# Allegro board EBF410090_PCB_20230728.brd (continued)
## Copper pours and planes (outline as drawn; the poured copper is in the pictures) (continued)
GND on BOTTOM: 69.22,21.26 69.29,21.08 69.47,21 73.66,21 73.84,21.08 73.91,21.26 73.91,25.37 73.84,25.55 73.66,25.63 69.47,25.63 69.29,25.55 69.22,25.37
GND on BOTTOM: 10.39,56.72 10.39,59.97 10.79,60.37 10.79,62.15 10.92,62.28 13.13,62.28 13.34,62.08 13.34,56.92 13.13,56.72
GND on BOTTOM: outline of 101 points within 0.51,8.51 136.49,89.49 ; 1 cut-out
GND on BOTTOM: 54.61,27.43 54.68,27.25 54.86,27.18 61.85,27.18 62.03,27.25 62.1,27.43 62.1,30.1 62.03,30.28 61.85,30.35 54.86,30.35 54.68,30.28 54.61,30.1
GND on BOTTOM: 127.08,84.07 127.08,78.82 125.15,78.82 125.15,80.47 124.84,80.77 123.65,80.77 123.47,80.95 123.47,83.49 124.05,84.07
GND on BOTTOM: 9.14,27.56 9.22,27.38 9.4,27.3 12.19,27.3 12.37,27.38 12.45,27.56 12.45,30.35 12.37,30.53 12.19,30.61 9.4,30.61 9.22,30.53 9.14,30.35
GND on BOTTOM: 7.01,51.61 7.08,51.43 7.26,51.36 9.25,51.36 9.43,51.43 9.5,51.61 9.5,55.8 9.43,55.98 9.25,56.06 7.26,56.06 7.08,55.98 7.01,55.8
GND on BOTTOM: 111.84,40.61 111.91,40.43 112.09,40.36 119.71,40.36 119.89,40.43 119.96,40.61 119.96,46.02 119.89,46.2 119.71,46.28 117.2,46.28 116.69,46.79 116.69,58.19 116.43,58.44 111.71,58.44 111.53,58.27 111.53,46.15 111.84,45.85
GND on BOTTOM: 131.34,76.07 131.34,78.26 131.09,78.51 128.63,78.51 128.19,78.94 128.19,80.34 128.63,80.77 130.91,80.77 131.32,80.36 131.32,79.81 132.33,78.79 132.33,76.07 132.13,75.87 131.55,75.87
GND on BOTTOM: 12.57,69.72 12.39,69.8 12.32,69.98 12.32,73.1 12.33,73.16 12.34,73.21 12.34,71.8 12.42,71.63 12.6,71.55 14.05,71.55 14.23,71.63 14.3,71.8 14.3,73.3 14.3,73.35 18.08,73.35 18.26,73.28 18.34,73.1 18.34,69.98 18.26,69.8 18.08,69.72
GND on BOTTOM: 127.56,61.92 127.63,61.74 127.81,61.67 129.34,61.67 129.52,61.74 129.59,61.92 129.59,64.03 129.52,64.21 129.34,64.29 127.81,64.29 127.63,64.21 127.56,64.03
GND on BOTTOM: 20.6,69.67 20.67,69.49 20.85,69.42 21.92,69.42 22.1,69.49 22.17,69.67 22.17,71.25 22.1,71.43 21.92,71.5 20.85,71.5 20.67,71.43 20.6,71.25
GND on BOTTOM: 72.14,26.49 72.21,26.31 72.39,26.24 74.4,26.24 74.58,26.31 74.65,26.49 74.65,28.02 74.58,28.19 74.4,28.27 72.39,28.27 72.21,28.19 72.14,28.02
GND on BOTTOM: 63.75,64.9 63.83,64.72 64.01,64.64 67.56,64.64 67.74,64.72 67.82,64.9 67.82,67.05 67.74,67.23 67.56,67.31 64.01,67.31 63.83,67.23 63.75,67.05
GND on BOTTOM: 123.49,19.28 123.57,19.1 123.75,19.02 125.68,19.02 125.86,19.1 125.93,19.28 125.93,25.86 125.86,26.04 125.68,26.11 123.75,26.11 123.57,26.04 123.49,25.86
GND on BOTTOM: 18.54,67.56 18.62,67.38 18.8,67.31 21.89,67.31 22.07,67.38 22.15,67.56 22.15,68.07 22.07,68.25 21.89,68.32 18.8,68.32 18.62,68.25 18.54,68.07
GND on BOTTOM: 14.53,67.89 14.53,64.06 14.22,63.75 11.07,63.75 10.79,63.47 10.79,61.67 10.95,61.52 16.03,61.52 16.26,61.75 16.26,67.66 16.03,67.89
GND on BOTTOM: 3.53,56.69 3.53,65.18 3.81,65.45 4.6,65.45 4.75,65.3 4.75,63.35 4.98,63.12 5.77,63.12 6.17,62.71 6.17,59.51 6.5,59.18 6.5,58.62 5.64,58.62 5.46,58.44 5.46,56.95 5.21,56.69
GND on BOTTOM: 96.14,43.79 96.21,43.61 96.39,43.53 99.62,43.53 99.8,43.61 99.87,43.79 99.87,45.21 99.8,45.39 99.62,45.46 96.39,45.46 96.21,45.39 96.14,45.21
GND on BOTTOM: 41.27,27.43 41.35,27.25 41.53,27.18 48.51,27.18 48.69,27.25 48.77,27.43 48.77,30.1 48.69,30.28 48.51,30.35 41.53,30.35 41.35,30.28 41.27,30.1
GND on BOTTOM: 100.58,40.11 100.66,39.93 100.84,39.85 103.76,39.85 103.94,39.93 104.01,40.11 104.01,42.62 103.94,42.8 103.76,42.87 100.84,42.87 100.66,42.8 100.58,42.62
GND on BOTTOM: 25.43,70.08 25.5,69.9 25.68,69.82 29.16,69.82 29.34,69.9 29.41,70.08 29.41,72.47 29.34,72.64 29.16,72.72 25.68,72.72 25.5,72.64 25.43,72.47
GND on BOTTOM: 18.92,27.63 19,27.45 19.18,27.38 30.05,27.38 30.23,27.45 30.3,27.63 30.3,30.2 30.23,30.38 30.05,30.45 19.18,30.45 19,30.38 18.92,30.2
GND on BOTTOM: 7.29,48.34 7.29,49.76 6.99,50.06 6.99,52.86 6.81,53.03 5.05,53.03 5,52.98 5,51.61 5.31,51.31 5.79,51.31 5.87,51.23 5.87,48.49 6.02,48.34
GND on GND02: 3.05,8.51 1.25,9.25 0.51,11.05 0.51,86.95 1.25,88.75 3.05,89.49 133.95,89.49 135.75,88.75 136.49,86.95 136.49,11.05 135.75,9.25 133.95,8.51
GND on ART03: 102.72,24.26 102.72,15.95 106.83,15.95 106.83,24.26
GND on ART03: 3.05,8.51 1.25,9.25 0.51,11.05 0.51,25.93 17.02,25.93 19.84,23.11 27.89,23.11 28.55,22.45 28.55,18.26 28.78,18.03 33.15,18.03 33.78,17.4 41.53,17.4 41.78,17.14 41.78,13.59 42.04,13.33 42.67,13.33 43.56,14.22 44.7,14.22 45.47,13.46 70.74,13.46 72.39,11.81 119.76,11.81 120.78,12.83 122.05,12.83 122.94,13.71 129.54,13.71 131.19,15.37 134.11,15.37 135.41,16.66 135.41,53.44 135.94,53.97 135.94,82.02 135.64,82.32 131.17,82.32 129.46,84.02 129.46,88.11 128.8,88.77 52.25,88.77 51.31,87.83 51.31,81.74 50.11,80.54 4.95,80.54 4.6,80.19 4.6,76.76 4.09,76.25 1.98,76.25 1.04,75.31 1.04,26.52 0.97,26.44 0.51,26.44 0.51,86.95 1.25,88.75 3.05,89.49 133.95,89.49 135.75,88.75 136.49,86.95 136.49,11.05 135.75,9.25 133.95,8.51
GND on ART04: 84.28,53.08 84.35,52.91 84.53,52.83 103.05,52.83 103.23,52.91 103.3,53.08 103.3,73.81 103.23,73.99 103.05,74.07 84.53,74.07 84.35,73.99 84.28,73.81
GND on ART04: 36.14,40.89 36.22,40.71 36.4,40.64 47.85,40.64 48.03,40.71 48.11,40.89 48.11,67.51 48.03,67.69 47.85,67.77 36.4,67.77 36.22,67.69 36.14,67.51
VCC3V3_SYS on TOP: 119.51,66.27 119.58,66.09 119.76,66.01 122.3,66.01 122.48,66.09 122.56,66.27 122.56,66.62 122.48,66.8 122.3,66.88 119.76,66.88 119.58,66.8 119.51,66.62
VCC3V3_SYS on TOP: 5.21,46.23 5.21,45.72 5.33,45.59 7.75,45.59 7.87,45.72 7.87,47.62 6.99,47.62 6.6,47.24 5.84,47.24 5.71,47.12 5.71,46.48 5.59,46.35 5.33,46.35
VCC3V3_SYS on TOP: 119.51,44.17 119.58,43.99 119.76,43.92 122.3,43.92 122.48,43.99 122.56,44.17 122.56,44.53 122.48,44.7 122.3,44.78 119.76,44.78 119.58,44.7 119.51,44.53
VCC3V3_SYS on BOTTOM: 2.29,47.7 7.54,47.7 7.87,47.37 7.87,45.59 7.8,45.52 2.51,45.52 2.29,45.74
VCC3V3_SYS on BOTTOM: 70.26,26.49 70.33,26.31 70.51,26.24 71.73,26.24 71.91,26.31 71.98,26.49 71.98,28.02 71.91,28.19 71.73,28.27 70.51,28.27 70.33,28.19 70.26,28.02
VCC3V3_SYS on BOTTOM: 11.3,30.99 11.38,30.81 11.56,30.73 12.83,30.73 13.01,30.81 13.08,30.99 13.08,32.13 13.01,32.31 12.83,32.38 11.56,32.38 11.38,32.31 11.3,32.13
VCC3V3_SYS on BOTTOM: 11.3,34.8 11.38,34.62 11.56,34.54 12.83,34.54 13.01,34.62 13.08,34.8 13.08,35.94 13.01,36.12 12.83,36.19 11.56,36.19 11.38,36.12 11.3,35.94
VCC3V3_SYS on ART04: 16.9,24.01 18.69,22.22 65.79,22.22 66.04,21.97 66.04,18.41 66.37,18.08 128.91,18.08 129.97,19.15 129.97,44.07 129.41,44.63 118.31,44.63 117.14,45.8 117.14,51 117.88,51.74 124.41,51.74 124.99,52.32 124.99,68.5 124.54,68.96 119.05,68.96 118.62,68.53 118.62,62.69 118.92,62.38 121.39,62.38 121.67,62.1 121.67,57.91 121.41,57.66 114.1,57.66 113.61,57.17 113.61,41.12 114.07,40.66 121.44,40.66 121.97,40.13 121.97,33.6 122.33,33.25 125.27,33.25 125.73,32.79 125.73,25.4 125.58,25.25 71.91,25.25 71.91,26.62 71.63,26.9 13.87,26.9 13.39,27.38 13.39,35.36 13.37,35.37 13.37,37.98 13.11,38.25 11.48,38.25 11.23,38.51 11.23,44.6 10.97,44.86 7.85,44.86 7.75,44.96 7.75,45.97 7.62,46.1 4.7,46.1 4.57,45.97 4.57,24.26 4.83,24 4.84,24.01
VCC5V0_SYS on TOP: 13.16,50.06 14.38,50.06 14.53,50.21 14.53,52.55 14.91,52.93 14.91,60.78 15.16,61.04 15.16,63.27 13.72,63.27 13.72,57.78 13.56,57.63 13.56,53.44 13,52.88 13,50.21
VCC5V0_SYS on TOP: 119.51,36.04 119.58,35.86 119.76,35.79 122.3,35.79 122.48,35.86 122.56,36.04 122.56,36.4 122.48,36.58 122.3,36.65 119.76,36.65 119.58,36.58 119.51,36.4
VCC5V0_SYS on TOP: 119.51,39.34 119.58,39.16 119.76,39.09 122.3,39.09 122.48,39.16 122.56,39.34 122.56,39.7 122.48,39.88 122.3,39.95 119.76,39.95 119.58,39.88 119.51,39.7
VCC5V0_SYS on TOP: 119.63,58.14 119.71,57.96 119.89,57.89 122.43,57.89 122.61,57.96 122.68,58.14 122.68,58.5 122.61,58.67 122.43,58.75 119.89,58.75 119.71,58.67 119.63,58.5
VCC5V0_SYS on TOP: 119.51,61.44 119.58,61.26 119.76,61.19 122.3,61.19 122.48,61.26 122.56,61.44 122.56,61.8 122.48,61.98 122.3,62.05 119.76,62.05 119.58,61.98 119.51,61.8
VCC5V0_SYS on BOTTOM: 18.85,51.66 18.92,51.48 19.1,51.41 19.94,51.41 20.12,51.48 20.19,51.66 20.19,52.86 20.12,53.04 19.94,53.11 19.1,53.11 18.92,53.04 18.85,52.86
VCC5V0_SYS on BOTTOM: 9.09,46.28 14.17,46.28 14.43,46.53 14.43,52.37 14.17,52.63 13.11,52.63 12.85,52.37 12.85,47.93 12.6,47.67 9.09,47.67
VCC5V0_SYS on ART04: 13.06,50.04 16.84,50.04 17.14,49.73 17.14,45.39 17.55,44.98 21.97,44.98 22.66,44.3 22.66,30.89 23.29,30.25 93.24,30.25 94.08,31.09 94.08,41.3 94.64,41.86 99.95,41.86 100.48,41.32 100.48,36.88 101.04,36.32 116.92,36.32 117.35,35.89 121.08,35.89 121.31,36.12 121.31,39.88 121.06,40.13 113.54,40.13 113.13,40.54 113.13,57.61 113.51,57.99 120.88,57.99 121.28,58.39 121.28,61.67 120.83,62.13 109.58,62.13 109.09,61.64 109.09,49.53 108.2,48.64 87.55,48.64 86.92,48 86.92,33.88 86.33,33.3 29.9,33.3 28.91,34.29 28.91,53.8 28.47,54.23 13.41,54.23 13.06,53.87
VCC5V0_SYS_2 on BOTTOM: 11.3,38.73 11.38,38.55 11.56,38.48 12.83,38.48 13.01,38.55 13.08,38.73 13.08,39.88 13.01,40.06 12.83,40.13 11.56,40.13 11.38,40.06 11.3,39.88
VCC5V0_SYS_2 on BOTTOM: 106.55,84.58 106.63,84.4 106.81,84.33 107.95,84.33 108.13,84.4 108.2,84.58 108.2,85.85 108.13,86.03 107.95,86.1 106.81,86.1 106.63,86.03 106.55,85.85
VCC5V0_SYS_2 on BOTTOM: 121.51,84.38 121.59,84.2 121.77,84.12 123.29,84.12 123.47,84.2 123.55,84.38 123.55,85.8 123.47,85.98 123.29,86.05 121.77,86.05 121.59,85.98 121.51,85.8
VCC5V0_SYS_2 on BOTTOM: 11.13,65.38 11.13,64.54 11.3,64.36 13.94,64.36 13.94,67 14.17,67.23 14.17,67.84 14.35,68.02 17.68,68.02 17.88,68.22 17.88,69.24 17.6,69.52 13.69,69.52 13.34,69.16 11.58,69.16 11.1,68.68 11.1,65.4
VCC5V0_SYS_2 on ART04: 29.97,33.63 29.29,34.31 29.29,53.92 28.7,54.51 26.64,54.51 26.49,54.66 26.49,60.02 26.04,60.48 24.82,60.48 24.46,60.83 24.46,66.34 24.13,66.67 8.89,66.67 8.51,66.29 8.51,48.77 9.78,47.5 13,47.5 13.36,47.14 13.36,38.76 13.13,38.53 11.61,38.53 11.43,38.71 11.43,44.63 11,45.06 8.15,45.06 8,45.21 8,46.1 7.75,46.35 4.83,46.35 4.57,46.61 4.57,72.9 4.83,73.15 31.24,73.15 31.52,72.87 31.52,37.54 32.08,36.98 48.34,36.98 49.68,35.64 62.76,35.64 63.45,36.32 82.4,36.32 83.21,37.13 83.21,51.26 83.95,51.99 105.66,51.99 106.43,52.75 106.43,68.55 106.81,68.93 114.68,68.93 115.21,69.47 115.21,74.55 114.38,75.39 114.38,78.71 113.97,79.12 106.86,79.12 106.4,79.58 106.4,84.68 106.86,85.14 109.5,85.14 109.75,84.89 122,84.89 122.33,84.56 122.33,82.6 122.12,82.4 118.64,82.4 118.26,82.02 118.26,62.71 117.98,62.43 109.35,62.43 108.71,61.8 108.71,49.81 108.05,49.15 87.3,49.15 86.46,48.31 86.46,34.11 85.98,33.63
VCC_12V on TOP: 123.37,31.65 123.44,31.47 123.62,31.39 124.59,31.39 124.77,31.47 124.84,31.65 124.84,34.06 124.77,34.24 124.59,34.31 123.62,34.31 123.44,34.24 123.37,34.06
VCC_12V on TOP: 11.25,77.42 13.74,77.42 14.1,77.06 14.1,67.66 14.48,67.28 16.79,67.28 17.12,66.95 17.12,64.54 14.1,64.54 12.88,63.32 12.88,60.27 12.34,59.74 1.78,59.74 1.6,59.92 1.6,61.52 1.8,61.72 6.02,61.72 6.48,62.18 6.48,64.54 7.04,65.1 9.88,65.1 10.13,65.35 10.13,68.58 10.87,69.32 10.87,77.04
VCC_12V on BOTTOM: 8.51,55.47 9.78,55.47 9.96,55.65 9.96,60.37 10.34,60.76 10.34,62.13 10.36,62.15 10.36,63.17 10.24,63.3 9.02,63.3 8.84,63.12 8.84,56.49 8.51,56.16
VCC_12V on BOTTOM: 96.34,41.22 96.42,41.04 96.6,40.97 100.63,40.97 100.81,41.04 100.89,41.22 100.89,43.03 100.81,43.21 100.63,43.28 96.6,43.28 96.42,43.21 96.34,43.03
VCC_12V on BOTTOM: 1.65,55.47 2.57,55.47 2.57,56.54 2.74,56.72 3.1,56.72 3.1,63.91 2.82,64.18 2.82,65.28 1.68,65.28 1.45,65.05 1.45,55.68
VCC_12V on BOTTOM: 16,43.81 16.08,43.63 16.26,43.56 17.53,43.56 17.71,43.63 17.78,43.81 17.78,44.96 17.71,45.14 17.53,45.21 16.26,45.21 16.08,45.14 16,44.96
VCC_12V on ART04: 8.84,48.94 10.03,47.75 13.23,47.75 13.67,47.32 13.67,27.66 14.2,27.13 71.75,27.13 72.14,26.75 72.14,25.65 72.24,25.55 124.74,25.55 125.37,26.19 125.37,32.69 125.07,32.99 122.33,32.99 121.97,32.64 121.97,31.57 121.69,31.29 100.36,31.29 99.97,31.67 99.97,41.17 99.62,41.53 94.82,41.53 94.41,41.12 94.41,30.45 93.88,29.92 22.99,29.92 22.38,30.53 22.38,44.04 21.69,44.73 17.32,44.73 16.79,45.26 16.79,49.63 16.51,49.91 13.13,49.91 12.8,50.24 12.8,54.15 13.16,54.51 25.93,54.51 26.09,54.66 26.09,60.02 25.81,60.3 24.56,60.3 24.18,60.68 24.18,66.17 23.93,66.42 9.14,66.42 8.84,66.12
VDD_3V3 on BOTTOM: 4.45,31.62 4.52,31.44 4.7,31.37 10.03,31.37 10.21,31.44 10.29,31.62 10.29,32.13 10.21,32.31 10.03,32.38 4.7,32.38 4.52,32.31 4.45,32.13
VDD_3V3 on BOTTOM: 12.7,74.6 14.71,74.6 14.88,74.42 14.88,71.91 14.71,71.73 13.82,71.73 13.64,71.91 13.64,73.38 13.34,73.68 12.7,73.68
VDD_3V3 on PWR05: 3.05,8.51 1.25,9.25 0.51,11.05 0.51,86.95 1.25,88.75 3.05,89.49 133.95,89.49 135.75,88.75 136.49,86.95 136.49,11.05 135.75,9.25 133.95,8.51
VDD_5V on TOP: 58.7,64.72 57.53,64.72 57.53,66.88 57.25,67.16 55.37,67.16 55.19,67.33 55.19,69.34 55.32,69.47 56.54,69.47 56.72,69.29 56.72,68.4 56.9,68.22 58.45,68.22 58.72,67.94 58.72,64.74
VDD_5V on BOTTOM: 18.82,46.79 18.9,46.61 19.08,46.53 19.89,46.53 20.07,46.61 20.14,46.79 20.14,50.37 20.07,50.55 19.89,50.62 19.08,50.62 18.9,50.55 18.82,50.37
VDD_5V on ART03: 19.66,48.39 34.14,48.39 34.44,48.08 34.44,41.15 34.21,40.92 32.77,40.92 32.49,41.2 32.49,44.35 32,44.83 19.63,44.83 19.35,45.11 19.35,48.08
VDD_5V on ART04: 32.33,40.54 32,40.87 32,72.9 32.26,73.15 56.39,73.15 56.77,72.77 56.77,68.88 56.13,68.25 36.14,68.25 35.64,67.74 35.64,41.02 35.15,40.54
HDMI_5V on TOP: 60.83,64.64 60.91,64.46 61.09,64.39 63.5,64.39 63.68,64.46 63.75,64.64 63.75,66.17 63.68,66.35 63.5,66.42 61.09,66.42 60.91,66.35 60.83,66.17
HDMI_5V on BOTTOM: 61.54,64.64 63.25,64.64 63.45,64.85 63.45,68.5 62.46,69.49 61.59,69.49 61.34,69.24 61.34,64.85
MINIPCIE_3V3 on BOTTOM: 108.92,42.16 110.52,42.16 110.69,41.99 110.69,41.65 111.48,41.65 111.48,44.32 111.68,44.53 111.68,45.64 111.38,45.95 111.38,57.05 111,57.43 110.44,57.43 110.24,57.63 109.88,57.63 109.68,57.43 109.32,57.43 108.92,57.02
RS485_1_A on TOP (solid shape): 68.25,17.5 68.33,17.52 68.4,17.5 69.1,16.8 68.33,15.97 67.55,16.8
USB OTG on TOP: 30.02,81.48 30.02,78.97 29.92,78.87 22.99,78.87 22.86,78.99 22.86,80.47 23.01,80.62 24.28,80.62 24.64,80.97 24.64,84.02 24.66,84.05 25.22,84.05 25.27,84 25.27,80.72 25.5,80.49 28.8,80.49 29.03,80.72 29.03,81.48 29.41,81.86 29.41,84.02 30,84.02 30.01,84.01 30.01,81.49
USB OTG on BOTTOM: 20.4,68.48 18.85,68.48 18.75,68.58 18.75,78.71 19,78.97 22.68,78.97 22.86,79.15 22.86,80.42 23.01,80.57 24.23,80.57 24.38,80.42 24.38,77.75 24.16,77.52 20.78,77.52 20.4,77.14
N02088 on TOP: 6.3,73.71 6.3,81.48 6.78,81.96 10.24,81.96 10.69,81.51 10.69,78.51 10.24,78.05 8.99,78.05 8.61,77.67 8.61,73.71 8.38,73.48 6.53,73.48
N03633 on BOTTOM: 4.95,52.04 4.95,54.28 4.06,54.28 4.06,52.58 3.99,52.5 3.51,52.5 3.51,51.89 4.8,51.89
N03641 on BOTTOM: 1.65,55.24 3.68,55.24 3.84,55.09 3.84,52.81 3.73,52.7 3.25,52.7 3.1,52.55 3.1,51.41 3.23,51.28 4.57,51.28 4.57,49.88 2.29,49.88 2.29,53.08 2.41,53.21 2.64,53.21 2.79,53.36 2.79,54.35 2.64,54.51 1.65,54.51
N28501 on BOTTOM: 4.04,67.69 6.43,67.69 6.58,67.54 6.58,66.47 6.48,66.37 5.71,66.37 5.61,66.47 5.61,66.7 5.51,66.8 4.04,66.8
N28533 on BOTTOM: 3.07,64.39 3.07,66.52 3.25,66.7 5.38,66.7 5.49,66.6 5.49,66.17 5.66,65.99 7.32,65.99 7.52,66.19 7.52,67.18 8.92,67.18 8.92,64.9 5.03,64.9 4.9,65.02 4.9,65.43 4.8,65.53 3.89,65.53 3.78,65.43 3.78,64.39
N15852295 on BOTTOM (solid shape): 29.65,75.27 29.62,75.17 29.52,75.12 28.21,75.25 28.74,75.82 29.32,76.35
N17423559 on BOTTOM: 11.81,52.04 11.81,54.28 10.92,54.28 10.92,52.58 10.85,52.5 10.49,52.5 10.49,51.89 11.66,51.89
N17423580 on BOTTOM: 8.51,55.24 10.54,55.24 10.69,55.09 10.69,52.81 10.59,52.7 10.11,52.7 9.96,52.55 9.96,51.41 10.08,51.28 11.43,51.28 11.43,49.88 9.14,49.88 9.14,53.08 9.27,53.21 9.5,53.21 9.65,53.36 9.65,54.35 9.5,54.51 8.51,54.51
N17466585 on BOTTOM: 69.34,42.19 66.62,42.19 66.14,42.67 65.91,42.67 65.91,41.22 66.09,41.05 67.79,41.05 67.94,40.89 67.94,40.31 68.12,40.13 69.34,40.13
N17592125 on BOTTOM: 102.08,45.08 104.42,45.08 104.57,44.93 104.57,44.14 102.13,44.14 102.08,44.19
N17592129 on BOTTOM: 101.12,41.78 101.12,43.79 101.3,43.97 105.11,43.97 105.33,44.19 105.33,44.45 106.71,44.45 106.71,42.19 103.4,42.19 103.2,42.39 103.2,42.77 102.97,43 101.96,43 101.83,42.87 101.83,41.78
N17685851 on TOP: 119.99,29.41 121.39,29.41 121.59,29.21 122.53,29.21 122.53,30.2 119.99,30.2
N17759502 on BOTTOM: 11.99,70.31 8.18,70.31 7.92,70.56 7.92,72.36 8.18,72.62 9.55,72.62 9.68,72.49 9.68,71.86 9.8,71.73 11.28,71.73 11.4,71.86 11.4,72.57 11.58,72.74 12.65,72.74 12.65,71.47 12.19,71.47 11.99,71.27
N18386455 on TOP: 122.53,32.38 121.03,32.38 120.8,32.16 120.8,31.01 119.99,31.01 119.99,33.04 120.22,33.27 122.53,33.27

Small or netless copper shapes (teardrops, artwork), in the pictures only: 16 on TOP, 31 on BOTTOM, 11 on ART04

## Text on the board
Ref Des/Silkscreen Bottom: E | SPI_D0 | GND | 2A | 2B | 1A | 1B | 3V3 | INT | RST | SCL | SDA | SCL0 | SDA0 | SCL1 | SDA1 | TX0 | RX0 | TX1 | RX1 | SIM CARD | TF CARD | MIPI CSI RX0 | MIPI CSI RX1 | 20230728 | EBF410090
Ref Des/Silkscreen Top: B | 12V | GND | 3V3 | 5V | RXD | TXD | NC | A | T1_232 | DC-12V | RTC | R1_232 | FAN | T2_232 | USB_OTG | SPKP | R2_232 | SPK | SPKN | EAR | 485_2A | 485_2B | 485_1A | MIC | 485_1B | HDMI | C | D | I2C0 | ETH0 | USB3.0 HOST/OTG | I2C1 | UART0 | USB2.0 HOST | UART1 | IR_REC | SARADC | PWRON | RESET | RECOVERY | INP | INN | RS485_2 | EDP TOUCH | RS485_1 | LVDS_TX0 | MIPI_DSI_TX1 | EDP DSI | EBF410090 | 20230728 | + | -
COMPVAL_TYPE_BOTTOM: A | C73 | C228 | C229 | C14 | C13 | C15 | C57 | C58 | R6 | C74 | C75 | L7 | D4 | R7 | L6 | C59 | R19 | L1 | C48 | U1 | L8 | D1 | L4 | Y1 | R5 | U3 | R2 | R9 | L2 | C9 | C199 | C201 | J1 | Y2 | R43 | C204 | C205 | C203 | C202 | C198 | C200 | U7 | U5 | R47 | R49 | R48 | R52 | R53 | R50 | U6 | R23 | R24 | MASKROM | U2 | U4 | C46 | C63 | L3 | C4 | R3 | C49 | R4 | R1 | C47 | C17 | R11 | R16 | L9 | L5 | R12 | R14 | R8 | C44 | C71 | C51 | C39 | C40 | C50 | C41 | C42 | C99 | C100 | R55 | R33 | R54 | R34 | R56 | R57 | R58 | R59 | R60 | R61
BODY_CENTER: C176 | C211 | C163 | C170 | C167 | C175 | C165 | C101 | R62 | C95 | C97 | C162 | C79 | C77 | C81 | C88 | C87 | C190 | C116 | C91 | C85 | C86 | C172 | C122 | C117 | R38 | C169 | C168 | R51 | C105 | C215 | C111 | C110 | C206 | C103 | C107 | C181 | R44 | C108 | C94 | C166 | C191 | C80 | C209 | C212 | C78 | C217 | C207 | C195 | C208 | C187 | C193 | C210 | C185 | C184 | C197 | C89 | C118 | C194 | C84 | C90 | C120 | C214 | C216 | C83 | C186 | C82 | C119 | C183 | C121 | C114 | C180 | C113 | C188 | C173 | C115 | C189 | C171 | C179 | C174 | R74 | C102 | C213 | C20 | C26 | C27 | C56 | R22 | C52 | C53 | C11 | C106 | C22 | C21 | C24 | C25 | C54 | C55 | D2 | C66 | C65 | C67 | C45 | R15 | C2 | C32 | C34 | R10 | C76 | R28 | R31 | R35 | C43 | C33 | R13 | R29 | C68 | C69 | D3 | C37 | C36 | C35 | R25 | C70 | C72 | C10 | C96 | C8 | C7 | C98 | R72 | R70 | C164 | R73 | R71 | Q1 | R45 | R67 | R63 | C226 | C225 | R46 | R66 | C139 | C137 | C131 | C136 | C123 | C154 | R39 | R40 | C231 | C230 | C61 | R32 | R30 | C62 | C60 | R27 | R26 | R20 | C64 | R21 | C112 | C23 | C3 | C6 | C5 | R18 | C196 | C1 | C192 | C12 | C19 | C104 | C30 | C18 | C28 | C31 | C109 | C16 | C29 | C93 | R17 | C92 | C38 | R68 | R69 | R36 | R37 | C227 | C222 | C223 | R65 | C224 | C182 | C221 | C177 | C219 | C218 | C178 | C220 | R41 | R64 | R42 | C133 | C141 | C130 | C138 | C126 | C134 | C155 | C142 | C125 | C129 | C158 | C124 | C144 | C132 | C128 | C160 | C127 | C150 | C140 | C161 | C148 | C143 | C147 | C156 | C153 | C135 | C151 | C152 | C146 | C145 | C149 | C159 | C157 | 20230523 | EBF410089
DEVICE_TYPE_BOTTOM: SS2 | A | SS1 | J2 | C73 | C228 | C229 | C14 | C13 | C15 | C57 | C58 | R6 | C74 | C75 | L7 | D4 | R7 | L6 | C59 | R19 | L1 | C48 | U1 | L8 | D1 | L4 | Y1 | R5 | U3 | R2 | R9 | L2 | C9 | C199 | C201 | Y2 | R43 | C204 | C205 | J1 | C203 | C202 | C198 | C200 | U7 | U5 | R47 | R49 | R48 | R52 | R53 | R50 | U6 | R23 | R24 | MASKROM | U2 | U4 | C46 | C63 | L3 | C4 | R3 | C49 | R4 | R1 | C47 | C17 | R11 | R16 | L9 | L5 | R12 | R14 | R8 | C44 | C71 | C51 | C39 | C40 | C50 | C41 | C42 | C99 | C100 | R55 | R33 | R54 | R34 | R56 | R57 | R58 | R59 | R60 | R61
DIMENSION: FIGURE | SIZE | 12.0 | 19.69 | 21.65 | 25.59 | 27.56 | 33.46 | 39.37 | 47.24 | 72.05 | 78.74 | 125.98 | 166.14 | 35.43 | 40.0 | 43.31 | 62.99 | 66.93 | 78.7 | 127.95 | 27.56x27.56 | 47.24x23.62 | 66.9x19.7 | 66.93x23.62 | 70.9x15.7 | 78.74x39.37 | 94.49x94.49 | 106.3x35.43 | DRILL CHART: TOP to BOTTOM | ALL UNITS ARE IN MILS | PLATED | NON-PLATED | QTY | 1260 | 2 | 19 | 30 | 4 | 14 | 8 | 1 | 3 | 18 | 10
